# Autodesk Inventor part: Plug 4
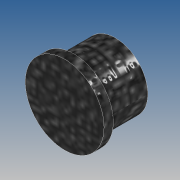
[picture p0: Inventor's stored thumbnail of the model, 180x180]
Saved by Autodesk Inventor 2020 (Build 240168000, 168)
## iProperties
Created: 2019-10
Part Number: Plug 4
Material: Generic
Document SubType Name: Modeling
Designer: yello
Density: 1 g/cm^3
Appearance: Default
Author: yello
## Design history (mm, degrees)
sketch "Sketch1"
  geometry: C1 r 4.25 at (0, 0); 1 further point
  constraints: 1 centre point, 1 coincident
  dimensions: "d0" = 8.5 diameter of C1
extrude "Extrusion1" new body sketch "Sketch1" distance "d1" = 1; taper "d2" = 0 deg
sketch "Sketch2"
  geometry: C1 r 3.5 at (0, 0); 1 further point
  constraints: 1 centre point, 1 coincident
  dimensions: "d3" = 7 diameter of C1
extrude "Extrusion2" join sketch "Sketch2" distance "d4" = 4.47; taper "d5" = 0 deg
body "Solid1"
